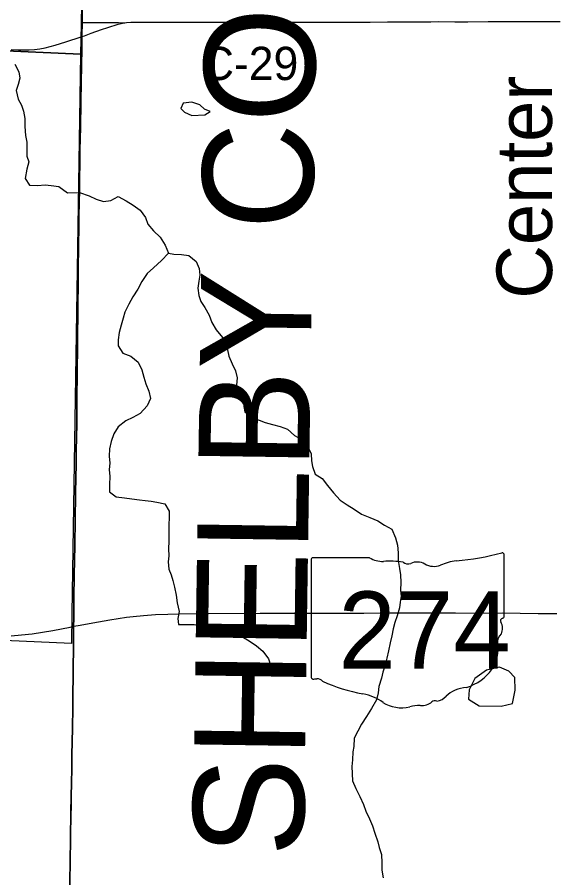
# Model space of a CAD drawing. Extents: x -11.1 to 34, y -3.9 to 22.
# Drawn here: x 7.271 to 8.187, y 15.825 to 17.295 of the extents above; entities that cross this region are included whole.
import ezdxf

# ---------------------------------------------------------------- set-up
doc = ezdxf.new("R2010")
doc.units = 0
for name, color, linetype in [('GM_X_Corporation', 7, 'Continuous'), ('GM_X_County_Road', 7, 'Continuous'), ('GM_X_County_Road_Text', 7, 'Continuous'), ('GM_X_County_Text', 7, 'Continuous'), ('GM_X_Minor_Lake', 7, 'Continuous'), ('GM_X_Minor_River', 7, 'Continuous'), ('GM_X_Minor_River_Text', 7, 'Continuous'), ('GM_X_State_Location', 7, 'Continuous'), ('GM_X_State_Route', 7, 'Continuous'), ('GM_X_State_Shield', 7, 'Continuous'), ('GM_X_Township_Road', 7, 'Continuous')]:
    doc.layers.add(name, color=color, linetype=linetype)

msp = doc.modelspace()

# ---------------------------------------------------------------- linework, layer by layer
at = {"layer": 'GM_X_Corporation'}
for points in [[(6.3851, 18.2506), (7.3955, 18.2326), (7.3797, 17.2828), (7.3791, 17.2313), (6.3727, 17.2765), (6.3791, 18.2511)], [(7.3791, 17.2313), (7.364, 16.2758), (7.3634, 16.2255), (6.3775, 16.2691), (6.3727, 17.2765)]]:
    msp.add_lwpolyline(points, close=True, dxfattribs=at)
for points in [[(7.3821, 17.3289), (7.3817, 17.2858), (7.3813, 17.2619), (7.381, 17.2413), (7.3804, 17.2121), (7.3798, 17.1829), (7.3793, 17.15), (7.3786, 17.1065), (7.3779, 17.0673), (7.3776, 17.0443), (7.3772, 17.0207), (7.3769, 16.999), (7.3764, 16.9778), (7.376, 16.9549), (7.3758, 16.9331), (7.3756, 16.9089), (7.3754, 16.8983), (7.3751, 16.8691), (7.3748, 16.8461), (7.3747, 16.8343), (7.3743, 16.8082), (7.3741, 16.7871), (7.3738, 16.7517), (7.3737, 16.7349), (7.373, 16.6871), (7.3728, 16.6436), (7.3724, 16.6001), (7.3716, 16.5541), (7.3712, 16.5323), (7.3704, 16.4833), (7.3698, 16.4329), (7.3692, 16.3969), (7.3685, 16.3633), (7.3683, 16.3466), (7.3677, 16.2987), (7.3673, 16.2676), (7.3671, 16.2554), (7.3669, 16.2447), (7.3669, 16.2316), (7.3667, 16.2111), (7.3665, 16.19), (7.3663, 16.1695), (7.3659, 16.1384), (7.3655, 16.1161), (7.3651, 16.0806), (7.3643, 16.0347), (7.3639, 16.0104), (7.3635, 15.9887), (7.3626, 15.9377), (7.3619, 15.8924), (7.3613, 15.8526), (7.3601, 15.7867)], [(7.3601, 15.7867), (7.3613, 15.8526), (7.3619, 15.8924), (7.3626, 15.9377), (7.3635, 15.9887), (7.3639, 16.0104), (7.3643, 16.0347), (7.3651, 16.0806), (7.3655, 16.1161), (7.3659, 16.1384), (7.3663, 16.1695), (7.3665, 16.19), (7.3667, 16.2111), (7.3669, 16.2316), (7.3669, 16.2447), (7.3671, 16.2554), (7.3673, 16.2676), (7.3677, 16.2987), (7.3683, 16.3466), (7.3685, 16.3633), (7.3692, 16.3969), (7.3698, 16.4329), (7.3704, 16.4833), (7.3712, 16.5323), (7.3716, 16.5541), (7.3724, 16.6001), (7.3728, 16.6436), (7.373, 16.6871), (7.3737, 16.7349), (7.3738, 16.7517), (7.3741, 16.7871), (7.3743, 16.8082), (7.3747, 16.8343), (7.3748, 16.8461), (7.3751, 16.8691), (7.3754, 16.8983), (7.3756, 16.9089), (7.3758, 16.9331), (7.376, 16.9549), (7.3764, 16.9778), (7.3769, 16.999), (7.3772, 17.0207), (7.3776, 17.0443), (7.3779, 17.0673), (7.3786, 17.1065), (7.3793, 17.15), (7.3798, 17.1829), (7.3804, 17.2121), (7.381, 17.2413), (7.3813, 17.2619), (7.3817, 17.2858), (7.3821, 17.3289)], [(7.3601, 15.7867), (7.3613, 15.8526), (7.3619, 15.8924), (7.3626, 15.9377), (7.3635, 15.9887), (7.3639, 16.0104), (7.3643, 16.0347), (7.3651, 16.0806), (7.3655, 16.1161), (7.3659, 16.1384), (7.3663, 16.1695), (7.3665, 16.19), (7.3667, 16.2111), (7.3669, 16.2316), (7.3669, 16.2447), (7.3671, 16.2554), (7.3673, 16.2676), (7.3677, 16.2987), (7.3683, 16.3466), (7.3685, 16.3633), (7.3692, 16.3969), (7.3698, 16.4329), (7.3704, 16.4833), (7.3712, 16.5323), (7.3716, 16.5541), (7.3724, 16.6001), (7.3728, 16.6436), (7.373, 16.6871), (7.3737, 16.7349), (7.3738, 16.7517), (7.3741, 16.7871), (7.3743, 16.8082), (7.3747, 16.8343), (7.3748, 16.8461), (7.3751, 16.8691), (7.3754, 16.8983), (7.3756, 16.9089), (7.3758, 16.9331), (7.376, 16.9549), (7.3764, 16.9778), (7.3769, 16.999), (7.3772, 17.0207), (7.3776, 17.0443), (7.3779, 17.0673), (7.3786, 17.1065), (7.3793, 17.15), (7.3798, 17.1829), (7.3804, 17.2121), (7.381, 17.2413), (7.3813, 17.2619), (7.3817, 17.2858), (7.3821, 17.3289)], [(7.3821, 17.3289), (7.3817, 17.2858), (7.3813, 17.2619), (7.381, 17.2413), (7.3804, 17.2121), (7.3798, 17.1829), (7.3793, 17.15), (7.3786, 17.1065), (7.3779, 17.0673), (7.3776, 17.0443), (7.3772, 17.0207), (7.3769, 16.999), (7.3764, 16.9778), (7.376, 16.9549), (7.3758, 16.9331), (7.3756, 16.9089), (7.3754, 16.8983), (7.3751, 16.8691), (7.3748, 16.8461), (7.3747, 16.8343), (7.3743, 16.8082), (7.3741, 16.7871), (7.3738, 16.7517), (7.3737, 16.7349), (7.373, 16.6871), (7.3728, 16.6436), (7.3724, 16.6001), (7.3716, 16.5541), (7.3712, 16.5323), (7.3704, 16.4833), (7.3698, 16.4329), (7.3692, 16.3969), (7.3685, 16.3633), (7.3683, 16.3466), (7.3677, 16.2987), (7.3673, 16.2676), (7.3671, 16.2554), (7.3669, 16.2447), (7.3669, 16.2316), (7.3667, 16.2111), (7.3665, 16.19), (7.3663, 16.1695), (7.3659, 16.1384), (7.3655, 16.1161), (7.3651, 16.0806), (7.3643, 16.0347), (7.3639, 16.0104), (7.3635, 15.9887), (7.3626, 15.9377), (7.3619, 15.8924), (7.3613, 15.8526), (7.3601, 15.7867)]]:
    msp.add_lwpolyline(points, dxfattribs=at)
at = {"layer": 'GM_X_County_Road'}
for p, q in [((7.3815, 17.2613), (7.3819, 17.2853)), ((7.3672, 16.236), (7.3673, 16.2549))]:
    msp.add_line(p, q, dxfattribs=at)
for points in [[(7.3819, 17.2853), (7.3824, 17.3284)], [(7.3815, 17.2613), (7.3855, 17.2628), (7.3972, 17.267), (7.4147, 17.2733), (7.4253, 17.2768), (7.4431, 17.2824), (7.4484, 17.2838), (7.4532, 17.2847), (7.4545, 17.2849)], [(7.3819, 17.2853), (7.3875, 17.2853), (7.4369, 17.2856), (7.4439, 17.2855), (7.4545, 17.2849)], [(7.4545, 17.2849), (7.4575, 17.2853), (7.4649, 17.2858), (7.476, 17.286), (7.4996, 17.2861), (7.5438, 17.2861), (7.5767, 17.2862), (7.6227, 17.2861), (7.6457, 17.2861), (7.6656, 17.286), (7.6867, 17.2861), (7.7084, 17.2861), (7.7482, 17.2858), (7.7725, 17.286), (7.8315, 17.2862), (7.847, 17.2862), (7.8539, 17.2862), (7.8731, 17.2863), (7.903, 17.2864), (7.9284, 17.2866), (7.9477, 17.2867), (7.9651, 17.2869), (7.9769, 17.2869), (7.9893, 17.287), (8.0179, 17.2869), (8.0397, 17.2869), (8.0745, 17.2871), (8.0832, 17.2871), (8.1117, 17.2871), (8.1267, 17.2871), (8.1372, 17.2872), (8.1503, 17.2873), (8.1975, 17.2872)], [(7.2606, 17.2393), (7.2733, 17.2388), (7.2824, 17.2386), (7.2914, 17.2389), (7.3005, 17.2396), (7.3094, 17.2408), (7.3183, 17.2424), (7.3272, 17.2445), (7.3358, 17.247), (7.3536, 17.2527), (7.3626, 17.2555), (7.3715, 17.2583), (7.3815, 17.2613)], [(7.3742, 16.7663), (7.3743, 16.7866), (7.3746, 16.8077), (7.3748, 16.8207), (7.3749, 16.8338), (7.375, 16.8456), (7.3753, 16.8686), (7.3757, 16.8978), (7.3758, 16.9083), (7.3759, 16.9205), (7.376, 16.9326), (7.3761, 16.9435), (7.3762, 16.9543), (7.3766, 16.9773), (7.3769, 16.9879), (7.3771, 16.9984), (7.3773, 17.0093), (7.3775, 17.0202), (7.3778, 17.0438), (7.378, 17.0553), (7.3781, 17.0668), (7.3786, 17.0957), (7.3788, 17.1059), (7.3791, 17.1246), (7.3793, 17.137), (7.3795, 17.1494), (7.3801, 17.1823), (7.3812, 17.2407), (7.3814, 17.251), (7.3815, 17.2613)], [(7.3673, 16.2549), (7.3676, 16.2671), (7.3679, 16.2982), (7.3686, 16.346), (7.3687, 16.3628), (7.3691, 16.3796), (7.3694, 16.3963), (7.37, 16.4324), (7.3703, 16.451), (7.3706, 16.4827), (7.3714, 16.5318), (7.3717, 16.5427), (7.3719, 16.5535), (7.3722, 16.5722), (7.3726, 16.5995), (7.3728, 16.6182), (7.3731, 16.643), (7.3731, 16.6617), (7.3732, 16.6741), (7.3735, 16.7052), (7.374, 16.7343), (7.3741, 16.7512), (7.3742, 16.7663)], [(7.361, 15.8235), (7.3615, 15.8521), (7.3618, 15.8707), (7.362, 15.8813), (7.3621, 15.8918), (7.3624, 15.9105), (7.3627, 15.9238), (7.3632, 15.9558), (7.3637, 15.9881), (7.3641, 16.0099), (7.3645, 16.0341), (7.3653, 16.0801), (7.3658, 16.1155), (7.3662, 16.1379), (7.3666, 16.1689), (7.3667, 16.1792), (7.3668, 16.1894), (7.367, 16.2106), (7.3671, 16.2311), (7.3672, 16.236)]]:
    msp.add_lwpolyline(points, dxfattribs=at)
at = {"layer": 'GM_X_Minor_Lake'}
for points in [[(7.5689, 17.1492), (7.5538, 17.1475), (7.5502, 17.1384), (7.5566, 17.1322), (7.5691, 17.1267)], [(7.5691, 17.1267), (7.5912, 17.1281), (7.6001, 17.1337), (7.5907, 17.1373), (7.5824, 17.1447), (7.5689, 17.1492)], [(8.0716, 16.1798), (8.0519, 16.1657), (8.0424, 16.1461), (8.041, 16.1301), (8.0595, 16.1188), (8.097, 16.1186)], [(8.097, 16.1186), (8.116, 16.123), (8.121, 16.1454), (8.1203, 16.1675), (8.1102, 16.1783), (8.0942, 16.1847), (8.0716, 16.1798)]]:
    msp.add_lwpolyline(points, dxfattribs=at)
at = {"layer": 'GM_X_Minor_River'}
for points in [[(7.267, 17.2141), (7.2735, 17.2014), (7.2751, 17.1907), (7.2726, 17.1794), (7.2693, 17.1696), (7.2727, 17.1547), (7.2781, 17.1443), (7.2813, 17.134), (7.2836, 17.1218), (7.2836, 17.1081), (7.2847, 17.0925), (7.2875, 17.0814), (7.2875, 17.0681), (7.2872, 17.0575), (7.2908, 17.0475), (7.287, 17.0351), (7.2843, 17.0192), (7.2916, 17.008), (7.3057, 17.0072), (7.3186, 17.0084)], [(7.3186, 17.0084), (7.3288, 17.0074), (7.3417, 17.0055), (7.3569, 16.9949), (7.3772, 16.9952)], [(7.3772, 16.9952), (7.3937, 16.9896), (7.4058, 16.984), (7.4179, 16.98), (7.4305, 16.9816), (7.4433, 16.9886), (7.4569, 16.9811), (7.4686, 16.9737), (7.4806, 16.9651), (7.4896, 16.9527), (7.4939, 16.9412), (7.5033, 16.93), (7.5149, 16.9191), (7.5234, 16.9056), (7.5289, 16.8918), (7.5172, 16.8791), (7.5036, 16.8668), (7.4928, 16.8567), (7.4837, 16.8436), (7.4766, 16.83), (7.4684, 16.8172), (7.4613, 16.8044), (7.4545, 16.7912), (7.4517, 16.781), (7.4484, 16.7689), (7.4451, 16.7564), (7.4434, 16.7438), (7.4432, 16.7336), (7.451, 16.7212), (7.465, 16.7156), (7.477, 16.7055), (7.4833, 16.6924), (7.4869, 16.6798), (7.4901, 16.6687), (7.4956, 16.656), (7.4984, 16.6438), (7.4929, 16.631), (7.4808, 16.6179), (7.4684, 16.6109), (7.4561, 16.6054), (7.4434, 16.5953), (7.4355, 16.5833), (7.4311, 16.5701), (7.4282, 16.5576), (7.4279, 16.545), (7.4289, 16.5332), (7.4279, 16.5221), (7.4288, 16.5103), (7.4282, 16.4966), (7.4284, 16.4844), (7.44, 16.4758), (7.4537, 16.4741), (7.4663, 16.4723), (7.4796, 16.4705), (7.4895, 16.4692), (7.4994, 16.4682), (7.5093, 16.4669), (7.523, 16.4636), (7.53, 16.4513), (7.5303, 16.4414), (7.5296, 16.4265), (7.5294, 16.4136), (7.5295, 16.3999), (7.5293, 16.3869), (7.5298, 16.3751), (7.5285, 16.3645), (7.5298, 16.3523), (7.5334, 16.3427), (7.5367, 16.3331), (7.5391, 16.3216), (7.5423, 16.3079), (7.5436, 16.2945), (7.5472, 16.28), (7.545, 16.2678), (7.546, 16.2579), (7.5601, 16.258), (7.5731, 16.2578), (7.5868, 16.2548), (7.6001, 16.2546), (7.6131, 16.254), (7.6261, 16.2526), (7.6404, 16.2451), (7.654, 16.2372), (7.6669, 16.2297), (7.6793, 16.2211), (7.6898, 16.2122), (7.6995, 16.199), (7.7039, 16.1864), (7.7071, 16.1749)], [(7.5289, 16.8918), (7.5384, 16.8901), (7.5514, 16.8895), (7.5639, 16.8877), (7.5763, 16.8776), (7.5815, 16.8657), (7.5824, 16.8542), (7.5811, 16.844), (7.5793, 16.8318), (7.581, 16.8193), (7.5843, 16.8093), (7.5909, 16.7989), (7.5987, 16.7858), (7.6031, 16.7731), (7.6105, 16.7608), (7.6213, 16.7477), (7.6272, 16.7377), (7.6297, 16.7266), (7.6318, 16.7159), (7.6377, 16.7028), (7.6432, 16.6909), (7.646, 16.6791), (7.645, 16.6665), (7.6478, 16.6543), (7.6575, 16.6419), (7.6577, 16.6301), (7.6591, 16.6206), (7.6707, 16.612), (7.684, 16.6064), (7.6939, 16.6028), (7.7068, 16.5991), (7.7197, 16.5958), (7.7322, 16.5914), (7.7442, 16.5805), (7.7567, 16.5738), (7.766, 16.5633), (7.7726, 16.5491), (7.7732, 16.5369), (7.7749, 16.5274), (7.7793, 16.5143), (7.7914, 16.5072), (7.8007, 16.4953), (7.8107, 16.4825), (7.822, 16.4701), (7.834, 16.4623), (7.8461, 16.4544), (7.8586, 16.4462), (7.8726, 16.4402), (7.8862, 16.4346), (7.8979, 16.4276), (7.9104, 16.4205), (7.9166, 16.4059), (7.9202, 16.3932), (7.9211, 16.3803), (7.9212, 16.3673), (7.9233, 16.3532), (7.925, 16.3425), (7.9255, 16.3296), (7.9253, 16.3162), (7.9259, 16.3059), (7.9245, 16.2957), (7.9236, 16.2862), (7.9191, 16.2726), (7.9155, 16.2612), (7.9126, 16.2506), (7.9105, 16.2385), (7.9072, 16.2263), (7.9047, 16.2127), (7.9018, 16.2002), (7.8989, 16.1892), (7.8949, 16.1763), (7.8924, 16.1664), (7.8883, 16.1521), (7.887, 16.141), (7.8841, 16.1289), (7.8758, 16.1146), (7.8672, 16.1007), (7.8585, 16.0879), (7.8459, 16.0637), (7.8453, 16.0497), (7.8439, 16.0402), (7.8433, 16.0269), (7.842, 16.0151), (7.843, 15.9907), (7.8489, 15.9776), (7.8555, 15.9642), (7.8618, 15.9507), (7.8661, 15.9392), (7.872, 15.9262), (7.8775, 15.9139), (7.8811, 15.9016), (7.8866, 15.8867), (7.8887, 15.8771), (7.8926, 15.8649), (7.8932, 15.8508), (7.8929, 15.8382), (7.8957, 15.8252)]]:
    msp.add_lwpolyline(points, dxfattribs=at)
at = {"layer": 'GM_X_State_Route'}
for points in [[(7.3673, 16.2549), (7.3783, 16.2568), (7.3997, 16.2605), (7.429, 16.2658), (7.4572, 16.2703), (7.4689, 16.2717), (7.4862, 16.2732), (7.5067, 16.2746), (7.5278, 16.2754), (7.547, 16.2759), (7.5973, 16.2765), (7.6855, 16.2769), (7.7495, 16.2771), (7.7968, 16.2774), (7.8222, 16.2773), (7.8626, 16.2774), (7.8968, 16.2776), (7.9564, 16.2777), (7.9962, 16.2777), (8.0192, 16.2777), (8.054, 16.2774), (8.0987, 16.2775), (8.1602, 16.2766), (8.1919, 16.2764)], [(7.2605, 16.2382), (7.2783, 16.2399), (7.2961, 16.2421), (7.3138, 16.2447), (7.3314, 16.2478), (7.3462, 16.2506), (7.3611, 16.2533), (7.3673, 16.2549)]]:
    msp.add_lwpolyline(points, dxfattribs=at)
at = {"layer": 'GM_X_State_Shield'}
for p, q in [((7.7725, 16.3683), (7.7725, 16.1682)), ((7.8723, 16.3718), (7.7757, 16.3718)), ((8.1021, 16.272), (8.1021, 16.3767)), ((8.102, 16.2721), (8.1021, 16.272))]:
    msp.add_line(p, q, dxfattribs=at)
for centre, major_axis, start_param, end_param in [((7.7763, 16.3687), (0.00382, 0), 1.712693, 3.28349), ((7.8952, 16.395), (0.037, 0), 4.042523, 4.731795), ((7.9075, 16.2594), (0.133, 0), 1.404758, 1.657858), ((8.0293, 16.3106), (0.0703, 0), 1.699011, 2.107814), ((7.9847, 16.6446), (0.3495, 0), 4.814394, 5.042369), ((8.0984, 16.3771), (0.00367, 0), 6.141152, 7.989035), ((7.9377, 16.3698), (0.0107, 0), 3.836095, 5.185415), ((7.9534, 16.3466), (0.0222, 0), 0.950623, 2.079405), ((7.9821, 16.3784), (0.0267, 0), 4.081561, 5.145723), ((8.1012, 16.2643), (0.00568, 0), 1.883978, 3.671073), ((8.0982, 16.2716), (0.00393, 0), 5.05454, 6.418171), ((8.0651, 16.2511), (0.0341, 0), 5.934695, 6.695948), ((8.1152, 16.2282), (0.0248, 0), 2.387724, 3.262537), ((8.0043, 16.2149), (0.0874, 0), 5.101752, 6.440018), ((7.7763, 16.1678), (0.00385, 0), 3.00124, 4.508301), ((7.7769, 16.1882), (0.0294, 0), 4.665946, 4.897461), ((7.7829, 16.1566), (0.0106, 0), 0.519207, 1.627899), ((7.9167, 16.3364), (0.2524, 0), 4.195997, 4.488961), ((8.0411, 16.112), (0.0479, 0), 1.647645, 2.488434), ((7.8415, 16.0783), (0.079, 0), 0.823519, 1.323587), ((7.9805, 16.1488), (0.0282, 0), 4.937069, 5.64225), ((7.9269, 16.1557), (0.0501, 0), 4.026481, 4.996735), ((7.9558, 16.0865), (0.0412, 0), 1.495662, 1.94098), ((7.9595, 16.1407), (0.0267, 0), 4.691044, 5.507374), ((7.9837, 16.1213), (0.00752, 0), 1.147584, 2.315152)]:
    msp.add_ellipse(centre, major_axis=major_axis, ratio=0.8, start_param=start_param, end_param=end_param, dxfattribs=at)
at = {"layer": 'GM_X_Township_Road'}
for p, q in [((7.3815, 17.2613), (7.3819, 17.2853)), ((7.3672, 16.236), (7.3673, 16.2549))]:
    msp.add_line(p, q, dxfattribs=at)
for points in [[(7.3819, 17.2853), (7.3824, 17.3284)], [(7.3742, 16.7663), (7.3743, 16.7866), (7.3746, 16.8077), (7.3748, 16.8207), (7.3749, 16.8338), (7.375, 16.8456), (7.3753, 16.8686), (7.3757, 16.8978), (7.3758, 16.9083), (7.3759, 16.9205), (7.376, 16.9326), (7.3761, 16.9435), (7.3762, 16.9543), (7.3766, 16.9773), (7.3769, 16.9879), (7.3771, 16.9984), (7.3773, 17.0093), (7.3775, 17.0202), (7.3778, 17.0438), (7.378, 17.0553), (7.3781, 17.0668), (7.3786, 17.0957), (7.3788, 17.1059), (7.3791, 17.1246), (7.3793, 17.137), (7.3795, 17.1494), (7.3801, 17.1823), (7.3812, 17.2407), (7.3814, 17.251), (7.3815, 17.2613)], [(7.3673, 16.2549), (7.3676, 16.2671), (7.3679, 16.2982), (7.3686, 16.346), (7.3687, 16.3628), (7.3691, 16.3796), (7.3694, 16.3963), (7.37, 16.4324), (7.3703, 16.451), (7.3706, 16.4827), (7.3714, 16.5318), (7.3717, 16.5427), (7.3719, 16.5535), (7.3722, 16.5722), (7.3726, 16.5995), (7.3728, 16.6182), (7.3731, 16.643), (7.3731, 16.6617), (7.3732, 16.6741), (7.3735, 16.7052), (7.374, 16.7343), (7.3741, 16.7512), (7.3742, 16.7663)], [(7.361, 15.8235), (7.3615, 15.8521), (7.3618, 15.8707), (7.362, 15.8813), (7.3621, 15.8918), (7.3624, 15.9105), (7.3627, 15.9238), (7.3632, 15.9558), (7.3637, 15.9881), (7.3641, 16.0099), (7.3645, 16.0341), (7.3653, 16.0801), (7.3658, 16.1155), (7.3662, 16.1379), (7.3666, 16.1689), (7.3667, 16.1792), (7.3668, 16.1894), (7.367, 16.2106), (7.3671, 16.2311), (7.3672, 16.236)]]:
    msp.add_lwpolyline(points, dxfattribs=at)

# ---------------------------------------------------------------- texts
at = {"layer": 'GM_X_County_Road_Text'}
msp.add_text('C-29', height=0.05682, rotation=0, dxfattribs=at).set_placement((7.5859, 17.1872))
at = {"layer": 'GM_X_County_Text'}
msp.add_text('SHELBY COUNTY', height=0.189394, rotation=89.1576, dxfattribs=at).set_placement((7.7595, 15.8606))
at = {"layer": 'GM_X_Minor_River_Text'}
msp.add_text('Center', height=0.09476, rotation=90.0581, dxfattribs=at).set_placement((8.1838, 16.814))
at = {"layer": 'GM_X_State_Location'}
for s in ['s', 'r']:
    msp.add_text(s, height=0.000189, dxfattribs=at).set_placement((7.9336, 16.2549))
msp.add_text('274', height=0.000189, rotation=0, dxfattribs=at).set_placement((7.8667, 16.2412))
at = {"layer": 'GM_X_State_Shield'}
msp.add_text('274', height=0.13184, dxfattribs=at).set_placement((7.819, 16.1823))

doc.saveas('drawing.dxf')
